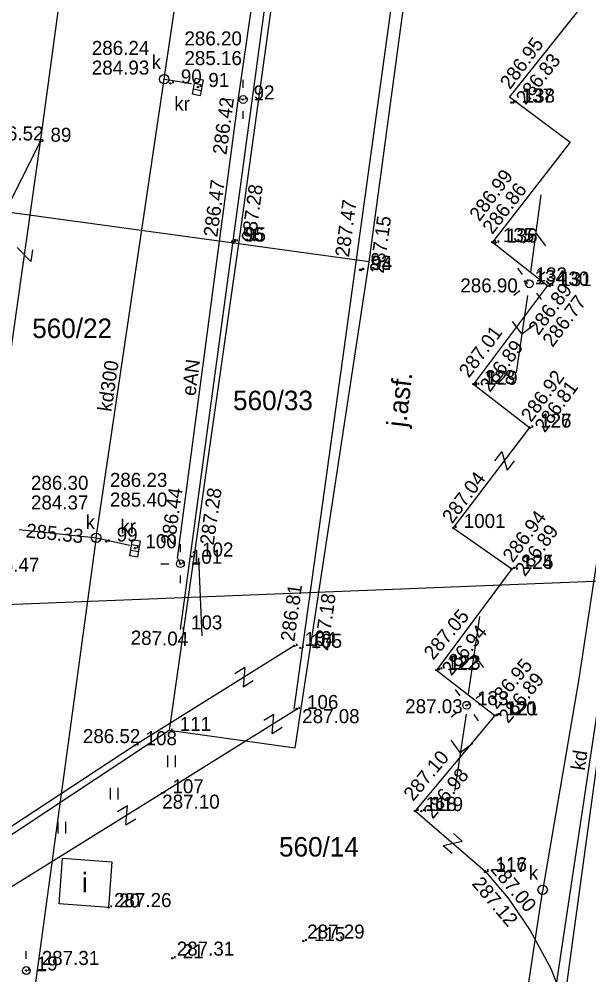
# Model space of a CAD drawing. Extents: x 4632591 to 4651936, y 5351032 to 5369988.
# Drawn here: x 4642774.3 to 4642810.8, y 5360075.1 to 5360136.4 of the extents above; entities that cross this region are included whole.
import ezdxf

# ---------------------------------------------------------------- set-up
doc = ezdxf.new("R2010")
doc.units = 0
for name, color, linetype in [('EBUPP_312', 7, 'Continuous'), ('EBUPP_316', 7, 'Continuous'), ('EDTTS_991', 7, 'Continuous'), ('EDZPD_211', 7, 'Continuous'), ('EDZPD_219', 7, 'Continuous'), ('SDRPK_420', 7, 'Continuous'), ('SDRPK_422', 7, 'Continuous'), ('SDRPK_432', 7, 'Continuous'), ('SDRPT_450', 7, 'Continuous'), ('SZZTZ_940', 7, 'Continuous'), ('UEEPA_510', 7, 'Continuous'), ('UEEPO_585', 7, 'Continuous'), ('UEETA_515', 7, 'Continuous'), ('UEETA_516', 7, 'Continuous'), ('UKKPA_506', 7, 'Continuous'), ('UKKPA_509', 7, 'Continuous'), ('UKKPO_582', 7, 'Continuous'), ('Warstwa 50', 7, 'Continuous'), ('Warstwa 62', 7, 'Continuous'), ('WUKPS_403', 7, 'Continuous')]:
    doc.layers.add(name, color=color, linetype=linetype)

msp = doc.modelspace()

# ---------------------------------------------------------------- linework, layer by layer
at = {"layer": 'EBUPP_316'}
msp.add_lwpolyline([(4642780.05, 5360079.43), (4642776.888, 5360079.666), (4642777.106, 5360082.588), (4642780.268, 5360082.353)], close=True, dxfattribs=at)
at = {"layer": 'EDTTS_991'}
for p, q in [((4642774.194, 5360121.719), (4642775.079, 5360120.836)), ((4642775.184, 5360121.578), (4642775.079, 5360120.836)), ((4642805.232, 5360108.655), (4642804.778, 5360108.058)), ((4642805.232, 5360108.655), (4642805.574, 5360107.453)), ((4642806.028, 5360108.05), (4642805.574, 5360107.453)), ((4642788.771, 5360094.802), (4642788.135, 5360094.404)), ((4642788.771, 5360094.802), (4642788.664, 5360093.556)), ((4642789.301, 5360093.953), (4642788.664, 5360093.556)), ((4642789.994, 5360091.427), (4642790.63, 5360091.825)), ((4642790.525, 5360090.58), (4642790.63, 5360091.825)), ((4642790.525, 5360090.58), (4642791.161, 5360090.978)), ((4642780.621, 5360085.572), (4642781.259, 5360085.967)), ((4642781.148, 5360084.722), (4642781.259, 5360085.967)), ((4642781.148, 5360084.722), (4642781.785, 5360085.117)), ((4642802.14, 5360084.164), (4642802.709, 5360083.675)), ((4642801.488, 5360083.406), (4642802.709, 5360083.675)), ((4642801.488, 5360083.406), (4642802.057, 5360082.917))]:
    msp.add_line(p, q, dxfattribs=at)
at = {"layer": 'EDZPD_219'}
for p, q in [((4642824.477, 5360185.186), (4642806.059, 5360050.143)), ((4642796.649, 5360182.126), (4642788.376, 5360121.952)), ((4642796.747, 5360120.803), (4642804.574, 5360178.838)), ((4642788.376, 5360121.952), (4642761.173, 5360125.677)), ((4642788.376, 5360121.952), (4642783.938, 5360090.788)), ((4642796.747, 5360120.803), (4642788.376, 5360121.952)), ((4642792.007, 5360089.667), (4642796.747, 5360120.803)), ((4642768.756, 5360080.751), (4642783.938, 5360090.788)), ((4642783.938, 5360090.788), (4642792.007, 5360089.667))]:
    msp.add_line(p, q, dxfattribs=at)
at = {"layer": 'SDRPK_420'}
msp.add_lwpolyline([(4642761.69, 5360099.87), (4642769.566, 5360116.28), (4642775.66, 5360128.5)], dxfattribs=at)
at = {"layer": 'SDRPK_422'}
for points in [[(4642800.957, 5360247.6), (4642789.673, 5360207.012), (4642785.643, 5360193.138), (4642783.61, 5360182.51), (4642781.64, 5360172.03), (4642777.96, 5360145.38), (4642775.66, 5360128.5)], [(4642810.67, 5360137.59), (4642805.721, 5360131.374), (4642809.607, 5360128.467), (4642804.64, 5360122.07), (4642808.16, 5360119.28), (4642803.42, 5360112.97), (4642807.02, 5360110.18), (4642802.13, 5360103.75), (4642805.87, 5360101.14), (4642801.05, 5360094.64), (4642804.79, 5360091.74), (4642799.68, 5360085.62), (4642804.17, 5360081.76)], [(4642775.66, 5360128.5), (4642771.89, 5360101.9), (4642769.07, 5360091.38), (4642765.92, 5360085.67)], [(4642791.94, 5360096.19), (4642781.75, 5360089.83), (4642767.44, 5360080.44), (4642764.88, 5360076.77), (4642763.38, 5360074.08)], [(4642764.35, 5360050.83), (4642761.64, 5360051.27), (4642760.53, 5360051.86), (4642759.78, 5360053.53), (4642759.44, 5360055.49), (4642761.99, 5360071.38), (4642762.41, 5360072.64), (4642763.38, 5360074.08), (4642765.05, 5360075.33), (4642783.47, 5360086.75), (4642792.09, 5360092.15)], [(4642804.17, 5360081.76), (4642805.635, 5360080.025), (4642807.058, 5360077.963), (4642808.388, 5360075.529), (4642809.479, 5360072.669), (4642809.892, 5360070.54), (4642810.277, 5360065.312), (4642808.309, 5360051.903), (4642807.51, 5360048.498), (4642804.318, 5360046.316), (4642803.147, 5360045.625), (4642800.167, 5360045.252), (4642793.676, 5360045.997), (4642788.993, 5360049.615), (4642769.518, 5360053.287), (4642764.35, 5360050.83)]]:
    msp.add_lwpolyline(points, dxfattribs=at)
at = {"layer": 'SDRPT_450'}
msp.add_line((4642784.66, 5360097.25), (4642799.288, 5360205.296), dxfattribs=at)
msp.add_lwpolyline([(4642807.866, 5360207.685), (4642795.027, 5360114.592), (4642791.918, 5360092.139)], dxfattribs=at)
at = {"layer": 'SZZTZ_940'}
for p, q in [((4642783.835, 5360088.428), (4642783.835, 5360089.178)), ((4642784.335, 5360088.428), (4642784.335, 5360089.178)), ((4642780.163, 5360086.353), (4642780.163, 5360087.103)), ((4642780.663, 5360086.353), (4642780.663, 5360087.103)), ((4642776.811, 5360084.171), (4642776.811, 5360084.921)), ((4642777.311, 5360084.171), (4642777.311, 5360084.921))]:
    msp.add_line(p, q, dxfattribs=at)
at = {"layer": 'UEEPA_510'}
for centre in [(4642788.67, 5360131.21), (4642807.002, 5360119.399), (4642784.65, 5360101.46), (4642802.99, 5360092.39), (4642774.78, 5360075.39)]:
    msp.add_circle(centre, 0.25, dxfattribs=at)
at = {"layer": 'UEEPO_585'}
for p, q in [((4642784.463, 5360101.826), (4642784.536, 5360101.682)), ((4642784.536, 5360101.682), (4642784.65, 5360101.46))]:
    msp.add_line(p, q, dxfattribs=at)
for points in [[(4642788.363, 5360131.302), (4642792.696, 5360161.34), (4642792.902, 5360161.318)], [(4642784.463, 5360101.826), (4642788.363, 5360131.302), (4642788.431, 5360131.282)], [(4642788.431, 5360131.282), (4642788.67, 5360131.21)]]:
    msp.add_lwpolyline(points, dxfattribs=at)
at = {"layer": 'UEETA_515'}
for p, q in [((4642788.67, 5360131.96), (4642788.67, 5360132.46)), ((4642787.42, 5360131.21), (4642787.92, 5360131.21)), ((4642789.42, 5360131.21), (4642789.92, 5360131.21)), ((4642788.67, 5360129.96), (4642788.67, 5360130.46)), ((4642806.25, 5360120.398), (4642806.551, 5360119.998)), ((4642808, 5360120.152), (4642807.601, 5360119.851)), ((4642806.403, 5360118.948), (4642806.004, 5360118.647)), ((4642807.454, 5360118.801), (4642807.755, 5360118.401)), ((4642784.65, 5360102.21), (4642784.65, 5360102.71)), ((4642783.4, 5360101.46), (4642783.9, 5360101.46)), ((4642785.4, 5360101.46), (4642785.9, 5360101.46)), ((4642784.65, 5360100.21), (4642784.65, 5360100.71)), ((4642802.246, 5360093.394), (4642802.543, 5360092.992)), ((4642803.592, 5360092.837), (4642803.994, 5360093.134)), ((4642801.986, 5360091.646), (4642802.388, 5360091.943)), ((4642803.437, 5360091.788), (4642803.734, 5360091.386)), ((4642774.78, 5360076.14), (4642774.78, 5360076.64)), ((4642775.53, 5360075.39), (4642776.03, 5360075.39))]:
    msp.add_line(p, q, dxfattribs=at)
at = {"layer": 'UEETA_516'}
for p, q in [((4642807.1, 5360120.143), (4642807.755, 5360125.1)), ((4642807.428, 5360122.622), (4642806.634, 5360122.013)), ((4642807.428, 5360122.622), (4642808.036, 5360121.828)), ((4642806.892, 5360118.658), (4642806.157, 5360113.712)), ((4642806.525, 5360116.185), (4642805.929, 5360116.988)), ((4642806.525, 5360116.185), (4642807.328, 5360116.78)), ((4642803.1, 5360093.132), (4642803.835, 5360098.078)), ((4642803.468, 5360095.605), (4642802.664, 5360095.009)), ((4642803.468, 5360095.605), (4642804.063, 5360094.802)), ((4642802.948, 5360091.829), (4642802.214, 5360086.884)), ((4642802.581, 5360089.356), (4642801.986, 5360090.16)), ((4642802.581, 5360089.356), (4642803.384, 5360089.952))]:
    msp.add_line(p, q, dxfattribs=at)
at = {"layer": 'UKKPA_506'}
for centre in [(4642783.614, 5360132.511), (4642779.26, 5360103.128), (4642807.856, 5360080.57)]:
    msp.add_circle(centre, 0.3, dxfattribs=at)
at = {"layer": 'UKKPA_509'}
for p, q in [((4642785.491, 5360131.885), (4642785.983, 5360131.791)), ((4642786.049, 5360132.135), (4642785.557, 5360132.229)), ((4642782.016, 5360102.581), (4642781.522, 5360102.664)), ((4642781.464, 5360102.319), (4642781.958, 5360102.236))]:
    msp.add_line(p, q, dxfattribs=at)
for points in [[(4642785.425, 5360131.542), (4642785.624, 5360132.573), (4642786.115, 5360132.478), (4642785.916, 5360131.447)], [(4642781.407, 5360101.974), (4642781.58, 5360103.009), (4642782.073, 5360102.926), (4642781.9, 5360101.891)]]:
    msp.add_lwpolyline(points, close=True, dxfattribs=at)
at = {"layer": 'UKKPO_582'}
for p, q in [((4642813.679, 5360117.261), (4642810.154, 5360093.953)), ((4642774.319, 5360103.647), (4642778.484, 5360103.21))]:
    msp.add_line(p, q, dxfattribs=at)
for points in [[(4642783.658, 5360132.808), (4642788.665, 5360166.614)], [(4642783.57, 5360132.215), (4642783.614, 5360132.511), (4642783.909, 5360132.463)], [(4642783.614, 5360132.511), (4642783.658, 5360132.808)], [(4642783.909, 5360132.463), (4642785.37, 5360132.224)], [(4642779.304, 5360103.425), (4642783.57, 5360132.215)], [(4642778.484, 5360103.21), (4642778.962, 5360103.16)], [(4642778.962, 5360103.16), (4642779.26, 5360103.128), (4642779.552, 5360103.062)], [(4642779.26, 5360103.128), (4642779.22, 5360102.831)], [(4642779.26, 5360103.128), (4642779.304, 5360103.425)], [(4642779.552, 5360103.062), (4642781.419, 5360102.639)], [(4642813.038, 5360103.272), (4642807.754, 5360068.11)], [(4642779.22, 5360102.831), (4642775.186, 5360073.205)], [(4642810.154, 5360093.953), (4642807.907, 5360080.866)], [(4642807.907, 5360080.866), (4642807.856, 5360080.57), (4642807.811, 5360080.274)], [(4642807.811, 5360080.274), (4642803.338, 5360050.72)]]:
    msp.add_lwpolyline(points, dxfattribs=at)
at = {"layer": 'Warstwa 50'}
for p, q in [((4642785.932, 5360099.329), (4642785.833, 5360101.827)), ((4642844.177, 5360101.636), (4642704.566, 5360096.106)), ((4642786.034, 5360096.829), (4642785.935, 5360099.327))]:
    msp.add_line(p, q, dxfattribs=at)
at = {"layer": 'WUKPS_403'}
for centre in [(4642784.01, 5360132.24), (4642785.77, 5360132.01), (4642788.67, 5360131.21), (4642805.84, 5360131.01), (4642805.97, 5360131.01), (4642775.66, 5360128.5), (4642787.98, 5360122.12), (4642788.12, 5360122.11), (4642804.64, 5360122.07), (4642804.85, 5360122.04), (4642796.16, 5360120.3), (4642796.21, 5360120.28), (4642806.73, 5360119.55), (4642808.16, 5360119.28), (4642808.31, 5360119.25), (4642803.42, 5360112.97), (4642803.57, 5360112.93), (4642807.02, 5360110.18), (4642807.03, 5360110.17), (4642802.13, 5360103.75), (4642779.9, 5360102.88), (4642781.74, 5360102.45), (4642785.37, 5360101.92), (4642784.65, 5360101.46), (4642805.84, 5360101.12), (4642805.87, 5360101.14), (4642791.94, 5360096.19), (4642792.33, 5360096.07), (4642801.05, 5360094.64), (4642801.2, 5360094.69), (4642792.09, 5360092.15), (4642802.99, 5360092.39), (4642804.79, 5360091.74), (4642804.9, 5360091.75), (4642781.75, 5360089.83), (4642783.47, 5360086.75), (4642799.68, 5360085.62), (4642800.08, 5360085.61), (4642804.17, 5360081.76), (4642804.17, 5360081.71), (4642780.05, 5360079.43), (4642792.53, 5360077.28), (4642784.13, 5360076.18), (4642774.78, 5360075.39)]:
    msp.add_circle(centre, 0.045, dxfattribs=at)

# ---------------------------------------------------------------- texts
at = {"layer": 'EBUPP_312'}
msp.add_text('i', height=1.25, dxfattribs=at).set_placement((4642778.349, 5360080.401))
at = {"layer": 'EDZPD_211'}
for s, p in [('560/22', (4642775.158, 5360115.923)), ('560/33', (4642788.024, 5360111.298)), ('560/14', (4642790.969, 5360082.694))]:
    msp.add_text(s, height=1.25, dxfattribs=at).set_placement(p)
at = {"layer": 'SDRPK_432'}
msp.add_text('j.asf.', height=1.25, rotation=83.24121, dxfattribs=at).set_placement((4642799.102, 5360110.166))
at = {"layer": 'UEEPO_585'}
msp.add_text('eAN', height=0.9, rotation=82.46383, dxfattribs=at).set_placement((4642785.606, 5360112.177))
at = {"layer": 'UKKPA_506'}
for s, p in [('286.24', (4642778.975, 5360134.064)), ('284.93', (4642778.975, 5360132.804)), ('k', (4642782.808, 5360133.159)), ('kr', (4642784.255, 5360130.49)), ('286.30', (4642775.078, 5360106.195)), ('284.37', (4642775.078, 5360104.935)), ('k', (4642778.576, 5360103.682)), ('kr', (4642780.797, 5360103.406)), ('k', (4642806.965, 5360081.209))]:
    msp.add_text(s, height=0.9, dxfattribs=at).set_placement(p)
at = {"layer": 'UKKPA_509'}
for s, p in [('286.20', (4642784.908, 5360134.675)), ('285.16', (4642784.908, 5360133.415)), ('286.23', (4642780.133, 5360106.381)), ('285.40', (4642780.133, 5360105.121))]:
    msp.add_text(s, height=0.9, dxfattribs=at).set_placement(p)
at = {"layer": 'UKKPO_582'}
for s, rotation, p in [('kd300', 81.57313, (4642780.225, 5360111.169)), ('285.33', 354.00367, (4642774.719, 5360103.153)), ('kd', 81.454, (4642810.543, 5360088.179))]:
    msp.add_text(s, height=0.9, rotation=rotation, dxfattribs=at).set_placement(p)
at = {"layer": 'Warstwa 62'}
for s, p in [('. 90', (4642784.01, 5360132.24)), ('. 91', (4642785.77, 5360132.01)), ('. 92', (4642788.67, 5360131.21)), ('. 137', (4642805.84, 5360131.01)), ('. 138', (4642805.97, 5360131.01)), ('. 89', (4642775.66, 5360128.5)), ('. 96', (4642787.98, 5360122.12)), ('. 95', (4642788.12, 5360122.11)), ('. 135', (4642804.64, 5360122.07)), ('. 136', (4642804.85, 5360122.04)), ('. 93', (4642796.16, 5360120.3)), ('. 94', (4642796.21, 5360120.28)), ('. 134', (4642806.67, 5360119.37)), ('. 132', (4642806.73, 5360119.55)), ('. 130', (4642808.16, 5360119.28)), ('. 131', (4642808.31, 5360119.25)), ('. 128', (4642803.42, 5360112.97)), ('. 129', (4642803.57, 5360112.93)), ('. 126', (4642807.02, 5360110.18)), ('. 127', (4642807.03, 5360110.17)), ('. 1001', (4642802.13, 5360103.75)), ('. 1001', (4642802.13, 5360103.75)), ('. 1001', (4642802.13, 5360103.75)), ('. 1001', (4642802.13, 5360103.75)), ('. 99', (4642779.9, 5360102.88)), ('. 100', (4642781.74, 5360102.45)), ('. 101', (4642784.65, 5360101.46)), ('. 102', (4642785.37, 5360101.92)), ('. 124', (4642805.84, 5360101.12)), ('. 125', (4642805.87, 5360101.14)), ('. 103', (4642784.66, 5360097.25)), ('. 104', (4642791.94, 5360096.19)), ('. 105', (4642792.33, 5360096.07)), ('. 122', (4642801.05, 5360094.64)), ('. 123', (4642801.2, 5360094.69)), ('. 133', (4642802.99, 5360092.39)), ('. 106', (4642792.09, 5360092.15)), ('. 120', (4642804.79, 5360091.74)), ('. 121', (4642804.9, 5360091.75)), ('. 111', (4642783.94, 5360090.74)), ('. 108', (4642781.75, 5360089.83)), ('. 107', (4642783.47, 5360086.75)), ('. 118', (4642799.68, 5360085.62)), ('. 119', (4642800.08, 5360085.61)), ('. 116', (4642804.17, 5360081.76)), ('. 117', (4642804.17, 5360081.71)), ('. 20', (4642780.05, 5360079.43)), ('. 115', (4642792.53, 5360077.28)), ('. 21', (4642784.13, 5360076.18)), ('. 19', (4642774.78, 5360075.39))]:
    msp.add_text(s, height=0.9, dxfattribs=at).set_placement(p)
at = {"layer": 'WUKPS_403'}
for s, rotation, p in [('286.95', 53.33744, (4642805.767, 5360131.802)), ('286.83', 51.47404, (4642806.764, 5360130.818)), ('286.42', 82.28998, (4642787.595, 5360127.632)), ('286.99', 53.33744, (4642803.804, 5360123.342)), ('286.47', 82.28998, (4642787.01, 5360122.351)), ('287.28', 82.28998, (4642789.444, 5360122.058)), ('286.86', 52.17032, (4642804.629, 5360122.517)), ('287.47', 82.28998, (4642795.444, 5360121.074)), ('287.15', 82.28998, (4642797.665, 5360120.036)), ('286.89', 53.08654, (4642807.582, 5360116.052)), ('286.77', 53.08654, (4642808.487, 5360115.28)), ('287.01', 53.44164, (4642803.133, 5360113.318)), ('286.89', 53.44164, (4642804.476, 5360112.4)), ('286.92', 53.44164, (4642807.11, 5360110.472)), ('286.81', 53.44164, (4642807.988, 5360109.806)), ('287.04', 53.44164, (4642802.055, 5360103.967)), ('286.44', 81.89512, (4642784.276, 5360102.616)), ('287.28', 81.89512, (4642786.777, 5360102.616)), ('286.94', 53.44164, (4642805.939, 5360101.479)), ('286.89', 53.44164, (4642806.724, 5360100.588)), ('286.81', 82.11686, (4642791.945, 5360096.431)), ('287.18', 82.11686, (4642794.1, 5360095.845)), ('287.05', 50.13922, (4642800.845, 5360095.24)), ('286.94', 50.13922, (4642802.002, 5360094.229)), ('287.04', 358.44605, (4642781.456, 5360096.284)), ('286.95', 50.13922, (4642804.902, 5360092.087)), ('286.89', 50.13922, (4642805.647, 5360091.183)), ('287.10', 50.13922, (4642799.554, 5360086.188)), ('286.98', 50.13922, (4642800.818, 5360085.057)), ('287.00', 310.16905, (4642804.463, 5360081.865)), ('287.12', 310.16905, (4642803.279, 5360080.933))]:
    msp.add_text(s, height=0.9, rotation=rotation, dxfattribs=at).set_placement(p)
for s, p in [('286.52', (4642772.198, 5360128.583)), ('286.90', (4642802.581, 5360118.845)), ('286.47', (4642771.938, 5360100.947)), ('287.03', (4642799.049, 5360091.875)), ('287.08', (4642792.451, 5360091.243)), ('286.52', (4642778.403, 5360089.966)), ('287.10', (4642783.485, 5360085.762)), ('287.26', (4642780.399, 5360079.457)), ('287.29', (4642792.77, 5360077.435)), ('287.31', (4642784.416, 5360076.344)), ('287.31', (4642775.769, 5360075.745))]:
    msp.add_text(s, height=0.9, dxfattribs=at).set_placement(p)

doc.saveas('drawing.dxf')
